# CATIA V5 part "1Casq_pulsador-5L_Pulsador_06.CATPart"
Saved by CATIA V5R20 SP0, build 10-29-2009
Part number: 1Casq_pulsador-5L_Pulsador_06
Revision: ANY
Definition: UNKNOWN
Nomenclature: 1Casq_pulsador-5L_Pulsador_06
Source: Unknown
Bounding box of the stored display mesh (mm): x -6.142 to 6.142, y 0 to 15.3, z -6.3 to 6.3
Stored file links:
  C:\Users\Utente\Desktop\IO LAVORO\3D X SITO CF\CUMSA\3D files BE\BE 051317\1Casq_pulsador-5L_Pulsador_06.CATPart
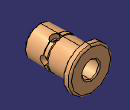
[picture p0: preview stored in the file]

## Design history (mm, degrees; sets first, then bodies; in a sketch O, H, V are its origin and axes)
Body1 "MatrizC1" (main body)
  Solid1: solid without history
